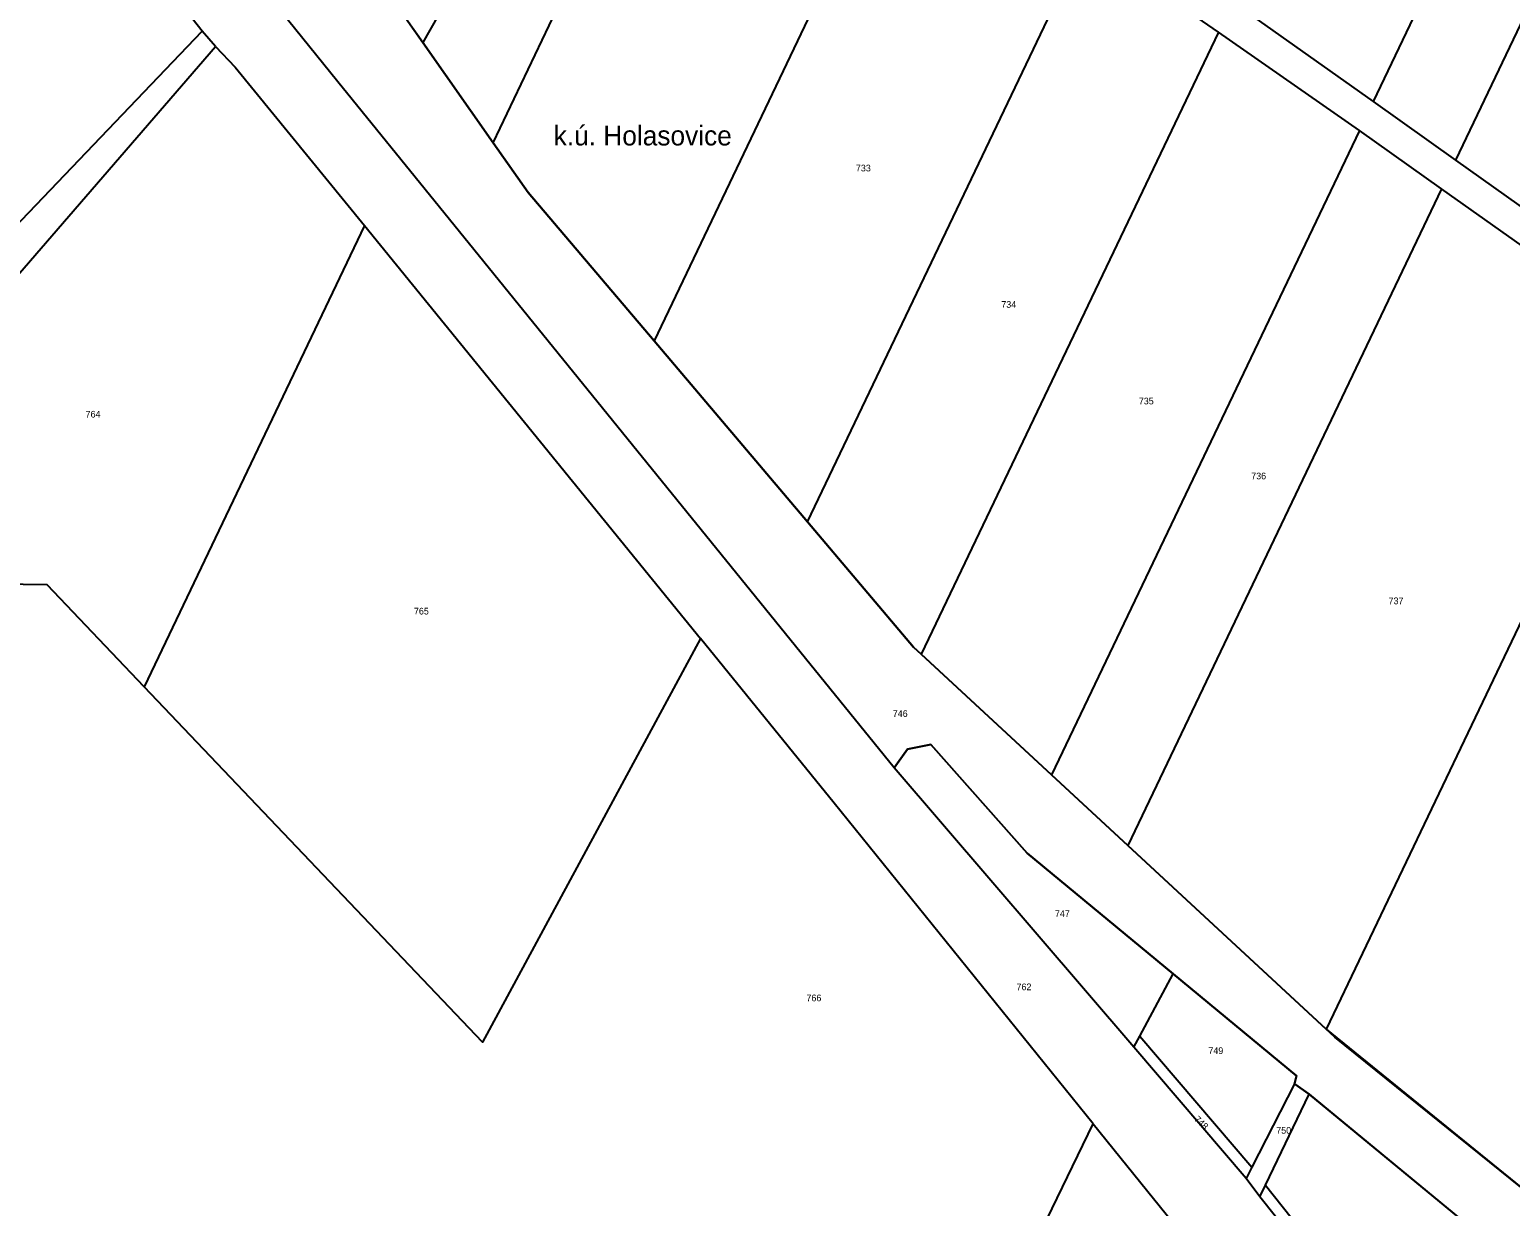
# Model space of a CAD drawing. Extents: x -504601 to -503665, y -1079870 to -1078626.
# Drawn here: x -504268.5 to -503891.4, y -1079448.1 to -1079148.4 of the extents above; entities that cross this region are included whole.
import ezdxf

# ---------------------------------------------------------------- set-up
doc = ezdxf.new("R2010")
doc.units = 0
for name, color, linetype in [('Hranice parcel', 7, 'Continuous'), ('Parcelní čísla', 7, 'Continuous'), ('Polygon ku', 7, 'Continuous'), ('Vrstva 54', 7, 'Continuous')]:
    doc.layers.add(name, color=color, linetype=linetype)

msp = doc.modelspace()

# ---------------------------------------------------------------- linework, layer by layer
at = {"layer": 'Hranice parcel'}
for p, q in [((-504150.39, -1079177.22), (-504094.24, -1079059.5)), ((-504045.55, -1079093.99), (-504109.47, -1079227.67)), ((-504168.33, -1079151.66), (-504187.04, -1079125.02)), ((-504070.38, -1079273.8), (-503999.6, -1079125.68)), ((-503965.74, -1079149.03), (-503999.6, -1079125.68)), ((-503960.91, -1079142.29), (-503926.36, -1079166.74)), ((-504221.12, -1079152.74), (-504224.49, -1079148.81)), ((-503965.74, -1079149.03), (-504041.43, -1079307.47)), ((-503929.86, -1079174.07), (-503965.74, -1079149.03)), ((-504150.39, -1079177.22), (-504168.33, -1079151.66)), ((-503926.36, -1079166.74), (-503905.42, -1079181.64)), ((-503929.86, -1079174.07), (-504008.27, -1079338.19)), ((-503908.92, -1079188.96), (-503929.86, -1079174.07)), ((-503905.42, -1079181.64), (-503850.5, -1079220.7)), ((-503908.92, -1079188.96), (-503988.82, -1079356.2)), ((-503854.56, -1079227.62), (-503908.92, -1079188.96)), ((-504183.22, -1079198.33), (-504239.26, -1079315.79)), ((-504183.22, -1079198.33), (-504097.67, -1079303.47)), ((-504070.38, -1079273.8), (-504109.47, -1079227.67)), ((-503854.56, -1079227.62), (-503938.33, -1079402.97)), ((-504008.27, -1079338.19), (-504041.43, -1079307.47)), ((-503987.33, -1079407.59), (-504048.32, -1079336.41)), ((-503988.82, -1079356.2), (-504008.27, -1079338.19)), ((-503938.33, -1079402.97), (-503988.82, -1079356.2)), ((-503985.81, -1079404.77), (-503977.25, -1079388.9)), ((-503987.33, -1079407.59), (-503985.81, -1079404.77)), ((-503985.81, -1079404.77), (-503957.24, -1079438.12)), ((-503958.71, -1079441.01), (-503987.33, -1079407.59)), ((-503946.4, -1079416.88), (-503957.24, -1079438.12)), ((-503953.77, -1079442.68), (-503942.64, -1079419.51)), ((-503946.4, -1079416.88), (-503942.64, -1079419.51)), ((-503942.64, -1079419.51), (-503895.86, -1079458.07)), ((-503997.67, -1079427.08), (-503950.22, -1079485.75)), ((-503957.24, -1079438.12), (-503958.71, -1079441.01)), ((-503955.21, -1079445.68), (-503958.71, -1079441.01)), ((-503955.21, -1079445.68), (-503953.77, -1079442.68)), ((-503953.77, -1079442.68), (-503912.97, -1079493.9))]:
    msp.add_line(p, q, dxfattribs=at)
for points in [[(-503787.07, -1078875.01), (-503845.26, -1078996.89), (-503926.36, -1079166.74)], [(-503758.93, -1078875.01), (-503827.49, -1079018.52), (-503905.42, -1079181.64)], [(-504048.32, -1079336.41), (-504164.13, -1079193.65), (-504189.98, -1079161.66), (-504303.4, -1079021.3), (-504338.19, -1078978.95)], [(-504113.31, -1079045.35), (-504120.83, -1079067.9), (-504168.33, -1079151.66)], [(-504224.49, -1079148.81), (-504231.2, -1079140.26), (-504237.3, -1079132.48)], [(-504343.18, -1079281.39), (-504285.23, -1079212.2), (-504231.96, -1079156.61), (-504224.49, -1079148.81)], [(-504331.73, -1079288.88), (-504307.23, -1079252.28), (-504221.12, -1079152.74)], [(-504221.12, -1079152.74), (-504216.11, -1079157.97), (-504183.22, -1079198.33)], [(-504109.47, -1079227.67), (-504141.49, -1079189.89), (-504150.39, -1079177.22)], [(-504041.43, -1079307.47), (-504043.38, -1079305.66), (-504070.38, -1079273.8)], [(-504239.26, -1079315.79), (-504263.96, -1079289.85), (-504331.73, -1079288.88)], [(-504097.67, -1079303.47), (-504153.14, -1079406.27), (-504239.26, -1079315.79)], [(-503997.67, -1079427.08), (-504063.57, -1079345.38), (-504097.67, -1079303.47)], [(-504048.32, -1079336.41), (-504044.97, -1079331.7), (-504038.99, -1079330.47), (-504014.44, -1079358.14), (-503977.25, -1079388.9)], [(-503977.25, -1079388.9), (-503945.84, -1079414.89), (-503946.4, -1079416.88)], [(-503888.76, -1079443.21), (-503936.1, -1079405.04), (-503938.33, -1079402.97)], [(-504131.58, -1079709.87), (-504110.18, -1079659.69), (-504032.95, -1079500.02), (-503997.67, -1079427.08)], [(-503697.84, -1079765.64), (-503779.17, -1079666.7), (-503806.76, -1079632.06), (-503843.08, -1079586.46), (-503955.21, -1079445.68)]]:
    msp.add_lwpolyline(points, dxfattribs=at)
at = {"layer": 'Vrstva 54'}
for points in [[(-503895.86, -1079458.07), (-503942.64, -1079419.51), (-503946.4, -1079416.88), (-503945.84, -1079414.89), (-503977.25, -1079388.9), (-504014.44, -1079358.14), (-504038.99, -1079330.47), (-504044.97, -1079331.7), (-504048.32, -1079336.41), (-504164.13, -1079193.65), (-504189.98, -1079161.66), (-504303.4, -1079021.3)], [(-504259.1, -1079048.24), (-504191.97, -1079119.35), (-504187.04, -1079125.02), (-504168.33, -1079151.66), (-504150.39, -1079177.22), (-504141.49, -1079189.89), (-504109.47, -1079227.67), (-504070.38, -1079273.8), (-504043.38, -1079305.66), (-504041.43, -1079307.47), (-504008.27, -1079338.19), (-503988.82, -1079356.2), (-503938.33, -1079402.97), (-503888.76, -1079443.21)]]:
    msp.add_lwpolyline(points, dxfattribs=at)

# ---------------------------------------------------------------- texts
at = {"layer": 'Parcelní čísla'}
for s, p in [('733', (-504058.07, -1079184.51)), ('734', (-504021.04, -1079219.25)), ('735', (-503986.03, -1079243.85)), ('764', (-504254.21, -1079247.2)), ('736', (-503957.41, -1079262.93)), ('765', (-504170.6, -1079297.36)), ('737', (-503922.44, -1079294.74)), ('746', (-504048.68, -1079323.43)), ('747', (-504007.38, -1079374.37)), ('766', (-504070.66, -1079395.86)), ('762', (-504017.17, -1079393.05)), ('762', (-504017.17, -1079393.05)), ('749', (-503968.32, -1079409.3)), ('750', (-503951.04, -1079429.6))]:
    msp.add_text(s, height=1.7, dxfattribs=at).set_placement(p)
msp.add_text('748', height=1.7, rotation=316, dxfattribs=at).set_placement((-503972.06, -1079426.09))
at = {"layer": 'Polygon ku'}
msp.add_text('k.ú. Holasovice', height=5, dxfattribs=at).set_placement((-504135.01, -1079177.9))

doc.saveas('drawing.dxf')
